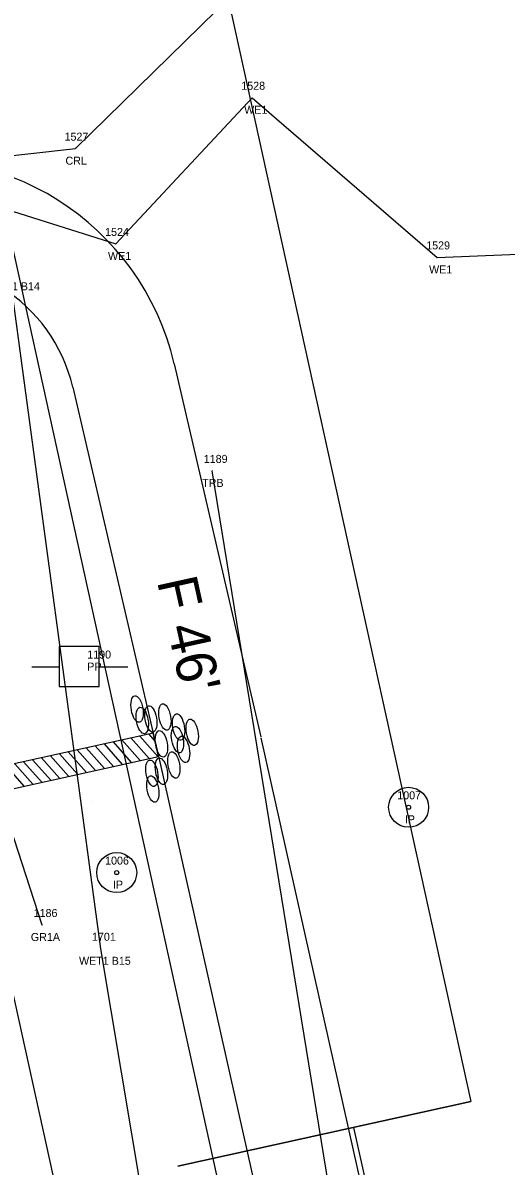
# Model space of a CAD drawing. Extents: x 2520975 to 2526538, y 881018 to 888064.
# Drawn here: x 2523838.7 to 2523899.1, y 884983.7 to 885126.5 of the extents above; entities that cross this region are included whole.
import ezdxf

# ---------------------------------------------------------------- set-up
doc = ezdxf.new("R2010")
doc.units = 0
for name, color, linetype in [('RD_EV_JurisArea', 7, 'Continuous'), ('RD_EX_DV_Prop', 7, 'Continuous'), ('RD_EX_DV_Prop_txCode', 7, 'Continuous'), ('RD_EX_DV_PropPin', 7, 'Continuous'), ('RD_EX_GuardRail', 7, 'Continuous'), ('RD_EX_GuardRail_txCode', 7, 'Continuous'), ('RD_EX_H2O', 7, 'Continuous'), ('RD_EX_H2O_txCode', 7, 'Continuous'), ('RD_EX_H2O_WetLd_txCode', 7, 'Continuous'), ('RD_EX_RW', 7, 'Continuous'), ('RD_EX_UT', 7, 'Continuous'), ('RD_EX_UT_txCode', 7, 'Continuous'), ('RD_EX_VEG', 7, 'Continuous'), ('RD_EX_VEG_txCode', 7, 'Continuous'), ('RD_HC_Cl', 7, 'Continuous'), ('RD_PD_CstnLmt', 7, 'Continuous'), ('RD_PD_DR_ErosCtrl', 7, 'Continuous'), ('RD_PD_Final_TrvlWay', 7, 'Continuous'), ('RD_PD_GR', 7, 'Continuous'), ('RD_PD_PaveShd', 7, 'Continuous'), ('RD_PD_RW', 7, 'Continuous'), ('RD_SMD_Locator', 7, 'Continuous')]:
    doc.layers.add(name, color=color, linetype=linetype)

msp = doc.modelspace()

# ---------------------------------------------------------------- linework, layer by layer
at = {"layer": 'RD_EV_JurisArea'}
msp.add_lwpolyline([(2523944.86, 884550.08), (2523910.41, 884709.58), (2523888.01, 884815.03), (2523863.93, 884918.37), (2523848.43, 885010.84), (2523837.07, 885095.13), (2523817.82, 885104.47)], dxfattribs=at)
at = {"layer": 'RD_EX_DV_Prop'}
for p, q in [((2523830.15, 885284.72), (2523894.67, 884991.74)), ((2523894.67, 884991.74), (2523858.04, 884983.68))]:
    msp.add_line(p, q, dxfattribs=at)
at = {"layer": 'RD_EX_DV_PropPin'}
for centre, radius in [((2523886.89, 885028.52), 2.5), ((2523886.89, 885028.52), 0.25), ((2523850.41, 885020.36), 2.5), ((2523850.41, 885020.36), 0.25)]:
    msp.add_circle(centre, radius, dxfattribs=at)
at = {"layer": 'RD_EX_GuardRail'}
msp.add_lwpolyline([(2523841.11, 885013.81), (2523827.6, 885055.26), (2523819.28, 885089.09)], dxfattribs=at)
at = {"layer": 'RD_EX_H2O'}
for points in [[(2523582.82, 884766.34), (2523598.11, 884856.98), (2523627.59, 884901.75), (2523623.76, 884928.28), (2523586.58, 884955.43), (2523600.94, 884974.12), (2523633.05, 884997.68), (2523679.17, 885037.05), (2523744.72, 885076.89), (2523769.38, 885099), (2523825.47, 885108.66), (2523825.47, 885108.66), (2523845.24, 885110.83), (2523890.25, 885154.93)], [(2523827.83, 885106), (2523850.3, 885098.92), (2523867.33, 885117.19), (2523890.44, 885097.24), (2523927.79, 885098.78), (2523966.35, 885109.5), (2523978.17, 885083.37)]]:
    msp.add_lwpolyline(points, dxfattribs=at)
at = {"layer": 'RD_EX_RW'}
for p in [(2523830.15, 885284.72), (2523858.04, 884983.67)]:
    msp.add_line(p, (2523894.67, 884991.74), dxfattribs=at)
at = {"layer": 'RD_EX_UT'}
for p, q in [((2523848.22, 885048.62), (2523843.22, 885048.62)), ((2523843.22, 885048.62), (2523843.22, 885043.62)), ((2523848.22, 885043.62), (2523848.22, 885048.62)), ((2523839.79, 885046.06), (2523843.26, 885046.06)), ((2523848.15, 885046.06), (2523851.79, 885046.06)), ((2523843.22, 885043.62), (2523848.22, 885043.62))]:
    msp.add_line(p, q, dxfattribs=at)
at = {"layer": 'RD_EX_VEG'}
msp.add_lwpolyline([(2523998.75, 884575.96), (2523966.17, 884559.06), (2523924.93, 884771.45), (2523880.33, 884960.16), (2523862.36, 885070.56)], dxfattribs=at)
at = {"layer": 'RD_HC_Cl'}
msp.add_line((2523662.65, 885798.93), (2524219.24, 883271.29), dxfattribs=at)
at = {"layer": 'RD_PD_CstnLmt'}
for p, q in [((2523844.92, 885081.02), (2523855.75, 885034.37)), ((2523855.75, 885034.37), (2523877.61, 884936.78))]:
    msp.add_line(p, q, dxfattribs=at)
msp.add_arc((2523825.44, 885076.49), 20, 13.0724, 102.4185, dxfattribs=at)
at = {"layer": 'RD_PD_DR_ErosCtrl'}
for p, q in [((2523857.58, 885083.96), (2523868.41, 885037.31)), ((2523868.44, 885037.21), (2523890.29, 884939.62))]:
    msp.add_line(p, q, dxfattribs=at)
msp.add_arc((2523825.44, 885076.49), 33, 13.0724, 102.4185, dxfattribs=at)
at = {"layer": 'RD_PD_Final_TrvlWay'}
msp.add_line((2523712.87, 885663.87), (2524066.74, 884056.87), dxfattribs=at)
at = {"layer": 'RD_PD_GR'}
msp.add_line((2523831.88, 885030.39), (2523990.48, 884310.15), dxfattribs=at)
at = {"layer": 'RD_PD_PaveShd'}
for p, q in [((2523854.96, 885037.79), (2523832.38, 885032.81)), ((2523849.95, 885036.69), (2523852.22, 885034.11)), ((2523849.95, 885036.69), (2523852.22, 885034.11)), ((2523851.06, 885036.93), (2523853.34, 885034.36)), ((2523851.06, 885036.93), (2523853.34, 885034.36)), ((2523852.18, 885037.18), (2523854.45, 885034.61)), ((2523852.18, 885037.18), (2523854.45, 885034.61)), ((2523853.3, 885037.42), (2523855.57, 885034.85)), ((2523853.3, 885037.42), (2523855.57, 885034.85)), ((2523854.41, 885037.67), (2523855.19, 885036.8)), ((2523855.63, 885034.87), (2523854.96, 885037.79)), ((2523844.36, 885035.45), (2523846.64, 885032.88)), ((2523844.36, 885035.45), (2523846.64, 885032.88)), ((2523845.48, 885035.7), (2523847.75, 885033.13)), ((2523845.48, 885035.7), (2523847.75, 885033.13)), ((2523846.6, 885035.95), (2523848.59, 885033.69)), ((2523846.6, 885035.95), (2523848.87, 885033.38)), ((2523847.71, 885036.19), (2523849.99, 885033.62)), ((2523847.71, 885036.19), (2523849.99, 885033.62)), ((2523848.83, 885036.44), (2523851.1, 885033.87)), ((2523848.83, 885036.44), (2523851.1, 885033.87)), ((2523833.02, 885029.88), (2523855.63, 885034.87)), ((2523837.66, 885033.97), (2523839.93, 885031.4)), ((2523837.66, 885033.97), (2523839.93, 885031.4)), ((2523838.78, 885034.22), (2523841.05, 885031.65)), ((2523838.78, 885034.22), (2523841.05, 885031.65)), ((2523839.89, 885034.47), (2523842.17, 885031.9)), ((2523839.89, 885034.47), (2523842.17, 885031.9)), ((2523841.01, 885034.71), (2523843.28, 885032.14)), ((2523841.01, 885034.71), (2523843.28, 885032.14)), ((2523842.13, 885034.96), (2523844.4, 885032.39)), ((2523842.13, 885034.96), (2523844.4, 885032.39)), ((2523843.24, 885035.21), (2523845.52, 885032.64)), ((2523843.24, 885035.21), (2523845.52, 885032.64)), ((2523836.54, 885033.73), (2523838.82, 885031.16))]:
    msp.add_line(p, q, dxfattribs=at)
for centre in [(2523852.95, 885040.8), (2523852.95, 885040.8), (2523853.61, 885039.37), (2523853.61, 885039.37), (2523854.67, 885039.57), (2523854.67, 885039.57), (2523856.43, 885039.8), (2523856.43, 885039.8), (2523858.15, 885038.54), (2523858.15, 885038.54), (2523859.85, 885037.9), (2523859.85, 885037.9), (2523855.99, 885036.45), (2523855.99, 885036.45), (2523858, 885036.98), (2523858, 885036.98), (2523858.77, 885035.75), (2523858.77, 885035.75), (2523857.55, 885033.81), (2523857.55, 885033.81), (2523854.81, 885032.78), (2523855.99, 885033.03), (2523855.99, 885033.03), (2523854.92, 885030.8)]:
    msp.add_ellipse(centre, major_axis=(0.29, -1.65), ratio=0.429445, dxfattribs=at)
at = {"layer": 'RD_PD_RW'}
msp.add_line((2523880.02, 884988.51), (2523987.54, 884500.21), dxfattribs=at)
at = {"layer": 'RD_SMD_Locator'}
for centre in [(2523867.33, 885117.19), (2523845.24, 885110.83), (2523850.3, 885098.92), (2523890.44, 885097.24), (2523862.36, 885070.56), (2523847.39, 885029.23), (2523841.11, 885013.81), (2523848.43, 885010.84)]:
    msp.add_circle(centre, 0.001, dxfattribs=at)

# ---------------------------------------------------------------- texts
at = {"layer": 'RD_EX_DV_Prop_txCode'}
for s, p in [('1007', (2523885.47, 885029.52)), ('IP', (2523886.42, 885026.52)), ('1006', (2523848.96, 885021.36)), ('IP', (2523849.94, 885018.36))]:
    msp.add_text(s, height=1, dxfattribs=at).set_placement(p)
at = {"layer": 'RD_EX_GuardRail_txCode'}
for s, p in [('1186', (2523840.03, 885014.81)), ('GR1A', (2523839.68, 885011.81))]:
    msp.add_text(s, height=1, dxfattribs=at).set_placement(p)
at = {"layer": 'RD_EX_H2O_txCode'}
for s, p in [('1528', (2523865.98, 885118.19)), ('WE1', (2523866.34, 885115.19)), ('1527', (2523843.89, 885111.83)), ('CRL', (2523844.01, 885108.83)), ('1524', (2523848.96, 885099.92)), ('1529', (2523889.09, 885098.24)), ('WE1', (2523849.32, 885096.92)), ('WE1', (2523889.45, 885095.24))]:
    msp.add_text(s, height=1, dxfattribs=at).set_placement(p)
at = {"layer": 'RD_EX_H2O_WetLd_txCode'}
for s, p in [('WET1 B14', (2523834.34, 885093.13)), ('1701', (2523847.32, 885011.84)), ('WET1 B15', (2523845.7, 885008.84))]:
    msp.add_text(s, height=1, dxfattribs=at).set_placement(p)
at = {"layer": 'RD_EX_UT_txCode'}
for s, p in [('1190', (2523846.73, 885047.11)), ('PP', (2523846.73, 885045.61))]:
    msp.add_text(s, height=1, dxfattribs=at).set_placement(p)
at = {"layer": 'RD_EX_VEG_txCode'}
for s, p in [('1189', (2523861.29, 885071.56)), ('TRB', (2523861.09, 885068.56))]:
    msp.add_text(s, height=1, dxfattribs=at).set_placement(p)
at = {"layer": 'RD_PD_CstnLmt'}
msp.add_text("F 46'", height=5, rotation=282.4185, dxfattribs=at).set_placement((2523855.43, 885056.8))

doc.saveas('drawing.dxf')
